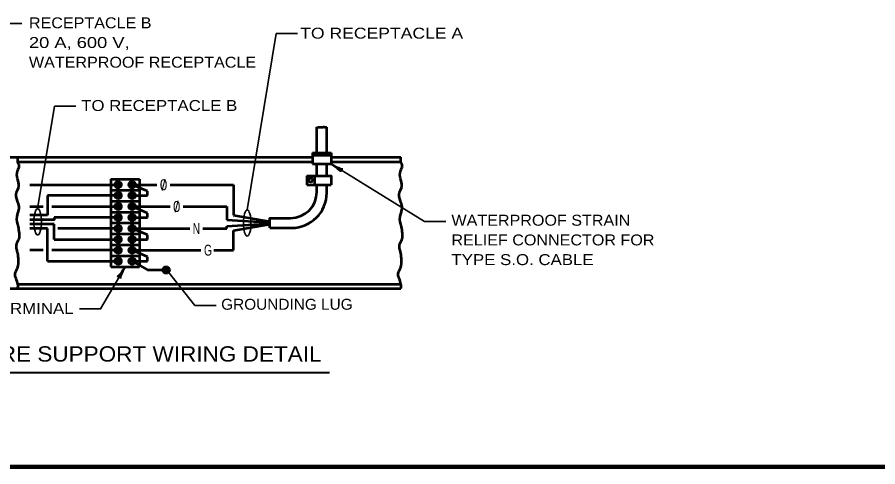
# Model space of a CAD drawing. Extents: x -24 to 689, y -7 to 446.
# Drawn here: x 135.8 to 332.4, y 2.2 to 105 of the extents above; entities that cross this region are included whole.
import ezdxf
from ezdxf.enums import TextEntityAlignment as Align

# ---------------------------------------------------------------- set-up
doc = ezdxf.new("R2010")
doc.units = 0
doc.layers.add('1', color=7, linetype='Continuous', lineweight=35)

msp = doc.modelspace()

# ---------------------------------------------------------------- hatches: boundary and pattern name
at = {"layer": '1'}
for points in [[(159.565, 66.709, 1), (158.065, 66.709, 1)], [(162.815, 66.709, 1), (161.315, 66.709, 1)], [(159.565, 64.209, 1), (158.065, 64.209, 1)], [(162.815, 64.209, 1), (161.315, 64.209, 1)], [(159.565, 61.709, 1), (158.065, 61.709, 1)], [(162.815, 61.709, 1), (161.315, 61.709, 1)], [(159.565, 59.209, 1), (158.065, 59.209, 1)], [(162.815, 59.209, 1), (161.315, 59.209, 1)], [(159.565, 56.709, 1), (158.065, 56.709, 1)], [(162.815, 56.709, 1), (161.315, 56.709, 1)], [(159.565, 54.209, 1), (158.065, 54.209, 1)], [(162.815, 54.209, 1), (161.315, 54.209, 1)], [(159.565, 51.709, 1), (158.065, 51.709, 1)], [(162.815, 51.709, 1), (161.315, 51.709, 1)], [(159.565, 49.209, 1), (158.065, 49.209, 1)], [(162.815, 49.209, 1), (161.315, 49.209, 1)], [(170.565, 47.209, 1), (169.065, 47.209, 1)]]:
    msp.add_hatch(color=256, dxfattribs=at).paths.add_polyline_path(points)

# ---------------------------------------------------------------- linework, layer by layer
for p, q in [((136.806, 103.541), (131.948, 103.541)), ((188.327, 60.927), (194.971, 101.232)), ((199.829, 101.232), (194.971, 101.232)), ((140.454, 61.219), (144.312, 84.621)), ((149.169, 84.621), (144.312, 84.621)), ((207.484, 71.459), (228.813, 58.324)), ((233.671, 58.324), (228.813, 58.324)), ((170.345, 46.678), (176.344, 39.074)), ((181.202, 39.074), (176.344, 39.074))]:
    msp.add_line(p, q, dxfattribs=at)
at = {"layer": '1', "lineweight": 53}
for p, q in [((204.234, 73.959), (204.234, 79.832)), ((206.484, 73.959), (206.484, 79.832)), ((126.94, 72.959), (135.94, 72.959)), ((135.94, 72.959), (203.234, 72.959)), ((203.234, 73.959), (207.484, 73.959)), ((203.234, 73.959), (203.234, 71.459)), ((203.234, 73.459), (207.484, 73.459)), ((207.484, 73.959), (207.484, 71.459)), ((207.484, 72.959), (223.44, 72.959)), ((135.94, 71.959), (203.234, 71.959)), ((203.234, 71.459), (207.484, 71.459)), ((204.234, 68.709), (204.234, 71.459)), ((206.484, 68.709), (206.484, 71.459)), ((207.484, 71.959), (223.44, 71.959)), ((157.19, 67.959), (163.69, 67.959)), ((163.69, 67.959), (163.69, 47.959)), ((201.949, 68.709), (201.949, 66.709)), ((203.699, 68.709), (203.699, 66.709)), ((138.69, 66.709), (158.065, 66.709)), ((157.19, 65.459), (163.69, 65.459)), ((165.565, 65.209), (162.065, 66.709)), ((162.815, 66.709), (167.69, 66.709)), ((165.565, 64.209), (165.565, 65.209)), ((170.69, 66.709), (185.19, 66.709)), ((185.19, 66.709), (185.19, 59.709)), ((201.949, 66.709), (207.484, 66.709)), ((204.234, 65.082), (204.234, 66.709)), ((206.484, 64.832), (206.484, 66.709)), ((158.815, 64.209), (142.69, 64.209)), ((142.69, 64.209), (142.69, 59.709)), ((157.19, 62.959), (163.69, 62.959)), ((162.065, 64.209), (165.565, 64.209)), ((138.69, 61.709), (141.69, 61.709)), ((143.69, 61.709), (159.565, 61.709)), ((165.565, 60.209), (162.065, 61.709)), ((162.815, 61.709), (170.69, 61.709)), ((173.69, 61.709), (183.69, 61.709)), ((183.69, 61.709), (183.69, 58.709)), ((142.69, 59.709), (138.69, 59.709)), ((158.815, 59.209), (144.19, 59.209)), ((157.19, 60.459), (163.69, 60.459)), ((162.065, 59.209), (165.565, 59.209)), ((165.565, 59.209), (165.565, 60.209)), ((185.19, 59.709), (193.484, 58.257)), ((144.19, 57.709), (138.69, 57.709)), ((144.19, 54.209), (144.19, 57.709)), ((157.19, 57.959), (163.69, 57.959)), ((183.69, 58.709), (193.484, 58.07)), ((183.69, 57.209), (193.484, 57.848)), ((183.69, 56.709), (183.69, 57.209)), ((185.19, 56.209), (193.484, 57.66)), ((142.69, 56.709), (138.69, 56.709)), ((142.69, 49.209), (142.69, 56.709)), ((158.815, 56.709), (145.073, 56.709)), ((157.19, 55.459), (163.69, 55.459)), ((162.065, 56.709), (175.19, 56.709)), ((165.565, 55.209), (162.065, 56.709)), ((165.565, 54.209), (165.565, 55.209)), ((178.19, 56.709), (183.69, 56.709)), ((185.19, 51.709), (185.19, 56.209)), ((193.484, 56.832), (198.484, 56.832)), ((144.19, 54.209), (159.565, 54.209)), ((162.065, 54.209), (165.565, 54.209)), ((141.69, 51.709), (138.69, 51.709)), ((158.815, 51.709), (143.69, 51.709)), ((157.19, 52.959), (163.69, 52.959)), ((162.065, 51.709), (177.69, 51.709)), ((165.565, 50.209), (162.065, 51.709)), ((180.69, 51.709), (185.19, 51.709)), ((142.69, 49.209), (158.065, 49.209)), ((157.19, 50.459), (163.69, 50.459)), ((162.065, 49.209), (165.565, 49.209)), ((162.065, 49.209), (165.565, 47.209)), ((165.565, 49.209), (165.565, 50.209)), ((157.19, 47.959), (163.69, 47.959)), ((165.565, 47.209), (169.815, 47.209)), ((135.94, 43.959), (223.44, 43.959))]:
    msp.add_line(p, q, dxfattribs=at)
at = {"layer": '1', "lineweight": 40}
msp.add_line((107.891, 23.773), (207.154, 23.773), dxfattribs=at)
at = {"layer": '1', "lineweight": 158}
msp.add_line((683.413, 2.23), (23.747, 2.23), dxfattribs=at)
at = {"layer": '1', "lineweight": 53}
for points in [[(157.19, 67.959), (157.19, 65.459), (157.19, 62.959), (157.19, 60.459), (157.19, 57.959), (157.19, 55.459), (157.19, 52.959), (157.19, 50.459), (157.19, 47.959)], [(201.949, 68.709), (207.484, 68.709), (207.484, 66.709)], [(144.19, 59.209), (144.19, 58.709), (138.69, 58.709)], [(193.484, 56.832), (193.484, 59.082), (198.234, 59.082)], [(100.44, 42.959), (135.94, 42.959), (223.44, 42.959)]]:
    msp.add_lwpolyline(points, dxfattribs=at)
at = {"layer": '1'}
msp.add_lwpolyline([(160.44, 47.959), (154.845, 38.322), (149.988, 38.322)], dxfattribs=at)
at = {"layer": '1', "lineweight": 53}
for centre, radius in [((158.815, 66.709), 0.75), ((162.065, 66.709), 0.75), ((202.82, 67.755), 0.469), ((158.815, 64.209), 0.75), ((162.065, 64.209), 0.75), ((158.815, 61.709), 0.75), ((162.065, 61.709), 0.75), ((158.815, 59.209), 0.75), ((162.065, 59.209), 0.75), ((158.815, 56.709), 0.75), ((162.065, 56.709), 0.75), ((158.815, 54.209), 0.75), ((162.065, 54.209), 0.75), ((158.815, 51.709), 0.75), ((162.065, 51.709), 0.75), ((158.815, 49.209), 0.75), ((162.065, 49.209), 0.75), ((169.815, 47.209), 0.75)]:
    msp.add_circle(centre, radius, dxfattribs=at)
for centre, radius in [((198.234, 65.082), 6), ((198.484, 64.832), 8)]:
    msp.add_arc(centre, radius, 270, 0, dxfattribs=at)
at = {"layer": '1', "lineweight": 40}
for centre, major_axis, ratio, start_param, end_param in [((208.327, 70.691), (1.403, -1.071), 0.07063, 6.2823074, 8.5597026), ((208.327, 70.691), (1.403, -1.071), 0.07063, 6.2823074, 8.5597026), ((208.558, 71.122), (-1.602, 0.803), 0.122415, 0.8963533, 3.1415927), ((208.558, 71.122), (-1.602, 0.803), 0.122415, 0.8963533, 3.1415927), ((159.694, 47.096), (-1.034, -1.431), 0.07063, 6.2823074, 8.5597026), ((160.131, 46.876), (0.761, 1.623), 0.122415, 0.8963533, 3.1415927)]:
    msp.add_ellipse(centre, major_axis=major_axis, ratio=ratio, start_param=start_param, end_param=end_param, dxfattribs=at)
at = {"layer": '1'}
for centre in [(140.454, 58.219), (188.327, 57.927)]:
    msp.add_ellipse(centre, major_axis=(0, -3), ratio=0.286071, dxfattribs=at)
at = {"layer": '1', "lineweight": 53}
for points in [[(204.234, 79.832), (204.351, 79.812), (204.471, 79.818), (204.626, 79.847), (204.718, 79.847), (204.821, 79.841), (204.936, 79.858), (205.045, 79.858), (205.235, 79.858), (205.303, 79.87), (205.435, 79.864), (205.63, 79.835), (205.699, 79.875), (205.814, 79.91), (205.952, 79.881), (206.038, 79.835), (206.147, 79.829), (206.267, 79.818), (206.348, 79.818), (206.484, 79.832)], [(135.94, 42.959), (135.94, 43.959), (135.326, 46.48), (135.927, 47.864), (136.047, 49.489), (135.927, 51.053), (135.686, 51.895), (135.686, 53.219), (136.228, 54.362), (136.288, 55.626), (136.047, 57.07), (135.747, 59.416), (136.168, 60.921), (136.047, 62.365), (135.506, 64.531), (136.168, 66.456), (135.867, 68.02), (135.867, 69.886), (136.228, 70.969), (135.94, 71.959), (135.94, 72.959)], [(223.44, 42.959), (223.44, 43.959), (222.826, 46.48), (223.427, 47.864), (223.547, 49.489), (223.427, 51.053), (223.186, 51.895), (223.186, 53.219), (223.728, 54.362), (223.788, 55.626), (223.547, 57.07), (223.247, 59.416), (223.668, 60.921), (223.547, 62.365), (223.006, 64.531), (223.668, 66.456), (223.367, 68.02), (223.367, 69.886), (223.728, 70.969), (223.44, 71.959), (223.44, 72.959)]]:
    msp.add_spline(points, degree=3, dxfattribs=at)

# ---------------------------------------------------------------- texts
at = {"layer": '1'}
for s, width, p in [('RECEPTACLE B', 1.1, (138.458, 102.445)), ('20 A, 600 V,', 1.25, (138.458, 97.945)), ('WATERPROOF RECEPTACLE', 1.1, (138.458, 93.445)), ('WATERPROOF STRAIN', 1.1, (234.977, 57.328)), ('RELIEF CONNECTOR FOR', 1.1, (234.977, 52.828)), ('TYPE S.O. CABLE', 1.15, (234.977, 48.328)), ('HEAVY DUTY TERMINAL', 1.15, (103.579, 37.176))]:
    msp.add_text(s, height=2.5, dxfattribs=dict(at, width=width)).set_placement(p)
for s, height, width, p in [('TO RECEPTACLE A', 2.5, 1.2, (219.041, 100.086)), ('TO RECEPTACLE B', 2.5, 1.15, (168.226, 83.543)), ('0', 2.5, 0.9, (169.219, 65.434)), ('0', 2.5, 0.9, (172.206, 60.47)), ('N', 2.5, 0.7, (176.712, 55.426)), ('G', 2.5, 0.7, (179.358, 50.489)), ('GROUNDING LUG', 2.5, 1.05, (197.392, 38.125)), ('LUMINAIRE SUPPORT WIRING DETAIL', 3.5, 1.1, (158.106, 26.273))]:
    msp.add_text(s, height=height, dxfattribs=dict(at, width=width)).set_placement(p, align=Align.CENTER)
for p in [(169.219, 65.391), (172.178, 60.386)]:
    msp.add_text('/', height=2.5, dxfattribs=at).set_placement(p, align=Align.CENTER)

doc.saveas('drawing.dxf')
